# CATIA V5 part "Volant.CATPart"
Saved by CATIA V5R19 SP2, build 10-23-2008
Part number: Volant
Bounding box of the stored display mesh (mm): x 0 to 30, y -150 to 150, z -149.99 to 149.99
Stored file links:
  C:\Users\Vianney\Documents\Garantie\Cours\2A\IAO\IAO-proj-Catia\Volant.CATPart
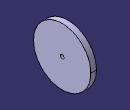
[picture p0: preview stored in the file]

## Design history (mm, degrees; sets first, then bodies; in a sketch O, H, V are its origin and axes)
Parameters
  Dv = 300 mm
  Ev = 30 mm
  Dav = 20 mm
Body1 (main body)
  Sketch1 on yz-plane, origin (0, 0, 0), H (0, 1, 0), V (0, 0, 1)
    circle A1 centre (0, 0) radius 150
    circle A2 centre (0, 0) radius 10
    radius A1 = 150 {= Dv /2}
    radius A2 = 10 {= Dav /2}
  Pad1: profile Sketch1, direction (1, 0, 0), length 30 {= Ev}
